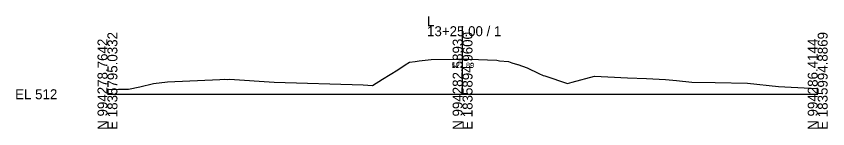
# Model space of a CAD drawing. Extents: x -26 to 2403, y -10 to 9558.
# Drawn here: x -25.7 to 202.8, y 490.3 to 521.9 of the extents above; entities that cross this region are included whole.
import ezdxf

# ---------------------------------------------------------------- set-up
doc = ezdxf.new("R2010")
doc.units = 0
for name, color, linetype in [('Exist Cross Section Cell', 7, 'Continuous'), ('Exist XS Center Line Elevation Label', 7, 'Continuous'), ('Exist XS Ground Line', 7, 'Continuous'), ('Scratch_Level_6', 7, 'Continuous')]:
    doc.layers.add(name, color=color, linetype=linetype)

msp = doc.modelspace()

# ---------------------------------------------------------------- linework, layer by layer
at = {"layer": 'Exist Cross Section Cell'}
for p, q in [((100, 500), (100, 519.11)), ((0, 500), (100, 500)), ((100, 500), (200, 500))]:
    msp.add_line(p, q, dxfattribs=at)
at = {"layer": 'Exist XS Ground Line'}
msp.add_lwpolyline([(0, 501.37), (3.11, 501.41), (5.92, 501.39), (9.13, 502.12), (12.99, 503.01), (16.9, 503.5), (31.65, 504.11), (32.93, 504.22), (33.75, 504.18), (34.37, 504.21), (46.96, 503.43), (72.04, 502.65), (74.6, 502.42), (77.42, 504.26), (81.76, 506.89), (83.82, 508.27), (85.07, 508.97), (86.66, 509.19), (87.74, 509.34), (91.11, 509.8), (99.04, 509.89), (100, 509.89), (100.36, 509.89), (101.86, 509.83), (109.6, 509.57), (110.42, 509.41), (112.92, 509.17), (113.44, 509.01), (113.86, 508.85), (115.47, 508.34), (115.57, 508.31), (118.16, 507.39), (121.52, 505.84), (122.7, 505.23), (123.2, 505.13), (129.56, 503.03), (130.89, 503.39), (137.15, 505.08), (140.91, 504.93), (146.48, 504.65), (151.78, 504.41), (157.11, 504.17), (160.28, 503.87), (164.57, 503.41), (171.09, 503.32), (180.27, 503.1), (188.99, 502.13), (197.98, 501.69), (200, 501.6)], dxfattribs=at)

# ---------------------------------------------------------------- texts
at = {"layer": 'Exist Cross Section Cell'}
for s, p in [('L', (90, 519.11)), ('13+25.00 / 1', (90, 516.31)), ('EL 512', (-26, 498.6))]:
    msp.add_text(s, height=2.8, dxfattribs=at).set_placement(p)
for s, p in [('E 1835795.0332', (2.8, 490)), ('E 1835894.9600', (102.8, 490)), ('E 1835994.8869', (202.8, 490)), ('N 994278.7642', (0, 490)), ('N 994282.5893', (100, 490)), ('N 994286.4144', (200, 490))]:
    msp.add_text(s, height=2.8, rotation=90, dxfattribs=at).set_placement(p)
at = {"layer": 'Exist XS Center Line Elevation Label'}
msp.add_text('521.89', height=1.5, dxfattribs=at).set_placement((96.93, 507.39))
at = {"layer": 'Scratch_Level_6'}
msp.add_text('-', height=0.01, dxfattribs=at).set_placement((0, 500))

doc.saveas('drawing.dxf')
